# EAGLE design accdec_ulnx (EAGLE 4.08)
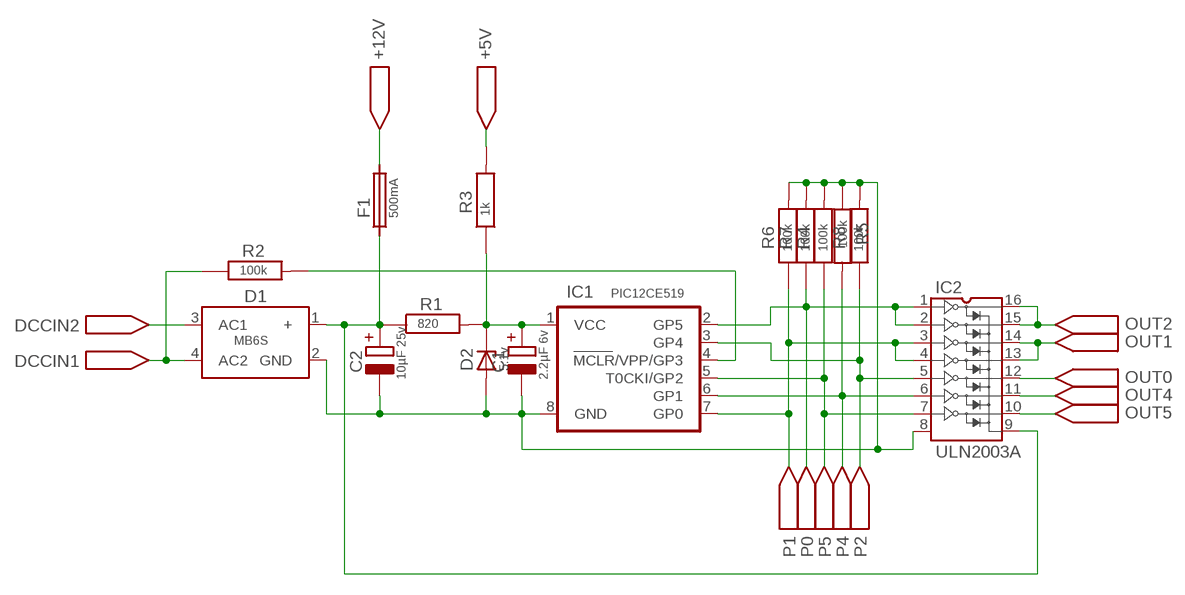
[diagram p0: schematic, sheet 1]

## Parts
+5V  PORT1*0.6  [CON_1*0.6]
+12V  PORT1.2*0.8  [CON_1.2*0.8]
C1  2.2µF 6v  ELKO_A  [CA]
C2  10µF 25v  ELKO_C  [CC]
D1  MB6S  [G1]
D2  5.1v  ZMM  [ZMM]
DCCIN1  PORT1*0.6  [CON_1*0.6]
DCCIN2  PORT1*0.6  [CON_1*0.6]
F1  500mA  FUSE  [1210]
IC1  PIC12CE519  PIC12CE519/SN  [SO8/SN]
IC2  ULN2003A  ULN2001A  [SO16]
OUT0  PORT1*0.6  [CON_1*0.6]
OUT1  PORT1*0.6  [CON_1*0.6]
OUT2  PORT1*0.6  [CON_1*0.6]
OUT4  PORT1*0.6  [CON_1*0.6]
OUT5  PORT1*0.6  [CON_1*0.6]
P0  PORT1*0.6  [CON_1*0.6]
P1  PORT1*0.6  [CON_1*0.6]
P2  PORT1*0.6  [CON_1*0.6]
P4  PORT1*0.6  [CON_1*0.6]
P5  PORT1*0.6  [CON_1*0.6]
R1  820  R-M1  [MICRO_MELF]
R2  100k  R-M1  [MICRO_MELF]
R3  1k  R-M1  [MICRO_MELF]
R4  100k  R-M1  [MICRO_MELF]
R5  100k  R-M1  [MICRO_MELF]
R6  100k  R-M1  [MICRO_MELF]
R7  100k  R-M1  [MICRO_MELF]
R8  100k  R-M1  [MICRO_MELF]

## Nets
+: C2.P$2(+) D1.1(+) F1.1 IC2.9(COM) R1.P$1
DCCIN: IC1.4(MCLR/VPP/GP3) R2.P$2
GND: C1.P$1(-) C2.P$1(-) D1.2(GND) D2.P$1(A) IC1.8(GND) IC2.8(GND) R4.P$2 R5.P$1 R6.P$2 R7.P$2 R8.P$2
GP0: IC1.7(GP0) IC2.3(IN3) IC2.4(IN4) P1.P$1 R6.P$1
GP1: IC1.6(GP1) IC2.6(IN6) P4.P$1 R5.P$2
GP2: IC1.5(T0CKI/GP2) IC2.7(IN7) P5.P$1 R4.P$1
GP4: IC1.3(GP4) IC2.5(IN5) P2.P$1 R8.P$1
GP5: IC1.2(GP5) IC2.1(IN1) IC2.2(IN2) P0.P$1 R7.P$1
N$1: D1.4(AC2) DCCIN1.P$1 R2.P$1
N$2: D1.3(AC1) DCCIN2.P$1
N$3: +5V.P$1 R3.P$2
N$4: +12V.P$1 F1.2
N$10: IC2.12(OUT5) OUT0.P$1
N$11: IC2.11(OUT6) OUT4.P$1
N$12: IC2.10(OUT7) OUT5.P$1
N$13: IC2.15(OUT2) IC2.16(OUT1) OUT2.P$1
N$14: IC2.13(OUT4) IC2.14(OUT3) OUT1.P$1
VCC: C1.P$2(+) D2.P$2(K) IC1.1(VCC) R1.P$2 R3.P$1

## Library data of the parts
+5V +12V DCCIN1 DCCIN2 OUT0 OUT1 OUT2 OUT4 OUT5 P0 P1 P2 P4 P5 = NMRA-DCC_Decoder_Parts:PORT
C1 C2 = NMRA-DCC_Decoder_Parts:ELKO
D1 = NMRA-DCC_Decoder_Parts:MB6S: Rectifier s380 & mb6s
D2 = NMRA-DCC_Decoder_Parts:ZMM: DIODE
F1 = NMRA-DCC_Decoder_Parts:FUSE
IC1 = NMRA-DCC_Decoder_Parts:PIC12C*?: PIC12Cx5xx 8 bit Microchip Microcontroller with 2k byte PROM and 16 byte EEPROM
IC2 = NMRA-DCC_Decoder_Parts:UL
R1-R8 = NMRA-DCC_Decoder_Parts:R-: Resistor

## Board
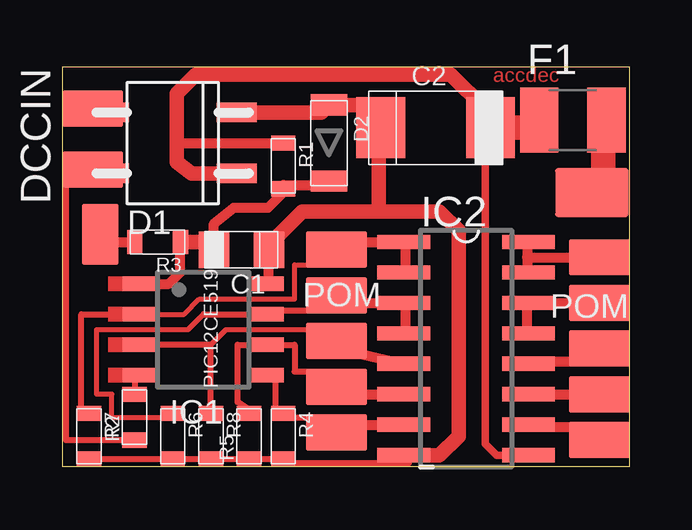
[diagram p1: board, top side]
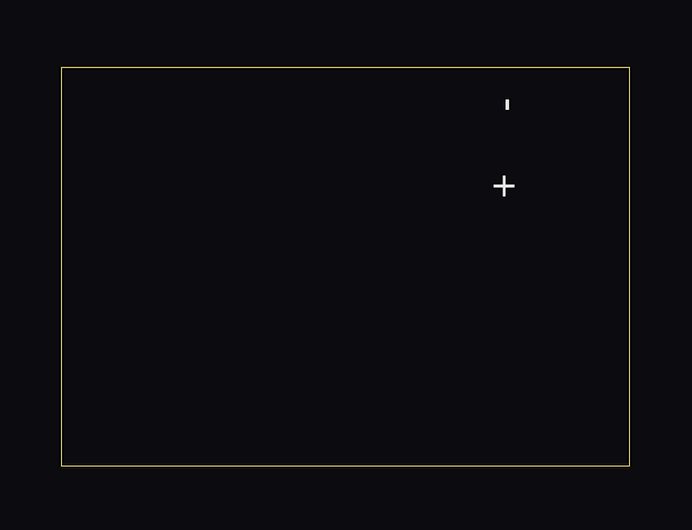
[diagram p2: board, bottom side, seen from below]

Size 23.64 x 16.66 mm. Coordinates in mm from the lower left corner, seen from the top.
Outline: 0,0 23.64,0 23.64,16.66 0,16.66 0,0
Copper layers used: Top

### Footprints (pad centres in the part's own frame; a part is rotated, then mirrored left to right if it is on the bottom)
CON_1*0.6 = smd 2.54 x 1.524: P$1 0,0
CON_1.2*0.8 = smd 3.048 x 2.032: P$1 0,0
CA = smd 1.27 x 1.524: P$1 -1.143,0; P$2 1.143,0
CC = smd 2.032 x 2.54: P$1 -2.286,0; P$2 2.286,0
G1 = smd 1.676 x 0.813: 1 3.302,-1.27; 2 3.302,1.27; 3 -2.032,1.27; 4 -2.032,-1.27
ZMM = smd 0.889 x 1.524: P$1 -1.587,0; P$2 1.587,0
1210 = smd 1.6 x 2.7: 1 -1.4,0; 2 1.4,0
SO8/SN = smd 0.61 x 1.524: 1 -1.905,-2.6; 2 -0.635,-2.6; 3 0.635,-2.6; 4 1.905,-2.6; 5 1.905,2.6; 6 0.635,2.6; 7 -0.635,2.6; 8 -1.905,2.6
SO16 = smd 0.6 x 2.2: 1 -4.445,-2.6; 2 -3.175,-2.6; 3 -1.905,-2.6; 4 -0.635,-2.6; 5 0.635,-2.6; 6 1.905,-2.6; 7 3.175,-2.6; 8 4.445,-2.6; 9 4.445,2.6; 10 3.175,2.6; 11 1.905,2.6; 12 0.635,2.6; 13 -0.635,2.6; 14 -1.905,2.6; 15 -3.175,2.6; 16 -4.445,2.6
MICRO_MELF = smd 0.635 x 1.016: P$1 -0.953,0; P$2 0.953,0

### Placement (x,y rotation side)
+5V  1.58,9.68 270 top
+12V  22.06,11.43 0 top
C1  7.46,9.04 180 top
C2  15.55,14.12 0 top
D1  3.96,13.49 0 top
D2  11.11,13.49 270 top
DCCIN1  1.26,12.38 180 top
DCCIN2  1.26,14.92 180 top
F1  21.27,14.44 0 top
IC1  5.87,5.71 270 top
IC2  16.82,4.92 270 top
OUT0  22.38,4.92 0 top
OUT1  22.38,6.82 0 top
OUT2  22.38,8.73 0 top
OUT4  22.38,3.01 0 top
OUT5  22.38,1.11 0 top
P0  11.42,9.04 0 top
P1  11.42,7.14 180 top
P2  11.42,5.23 0 top
P4  11.42,3.33 0 top
P5  11.42,1.42 0 top
R1  9.2,12.54 270 top
R2  3.01,2.06 90 top
R3  3.96,9.36 180 top
R4  9.2,1.27 270 top
R5  7.77,1.26 90 top
R6  4.6,1.27 270 top
R7  1.11,1.27 270 top
R8  6.18,1.27 270 top

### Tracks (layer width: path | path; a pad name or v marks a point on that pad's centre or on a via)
+
  Top 0.305: IC2.9 18.09,0.47 17.62,0.95 17.62,14.12
  Top 0.406: 4.76,13.49 R1.P$1 | 17.77,13.49 17.77,13.33 17.68,14.19 C2.P$2 17.77,14.28 17.77,13.49 | 17.62,14.92 17.77,13.49 | F1.1 19.84,14.12 20,13.97 19.68,14.12 | 19.68,14.12 | 19.68,14.12 | 17.62,14.12 19.68,14.12
  Top 0.61: D1.1 5.39,12.22 4.76,12.7 4.76,13.49 4.76,15.55 5.55,16.35 16.19,16.35 17.62,14.92
  Top 1.016: C2.P$2 19.68,14.12
DCCIN
  Top 0.254: IC1.4 | IC1.4 3.01,3.81 R2.P$2 | IC1.4
GND
  Top 0.254: R7.P$2 4.44,0.31 | 4.44,0.31 R6.P$2 4.44,0.31 | 4.44,0.31 R8.P$2 | R4.P$2 9.2,0.15 14.44,0.15 14.44,0.47 14.28,0.41 IC2.8 | R5.P$1 | R8.P$2 | R8.P$2 R5.P$1 | R4.P$2 R5.P$1 | R4.P$2 | R5.P$1
  Top 0.406: 8.41,9.52 C1.P$1 | 8.41,9.52 | 13.17,10.63 13.17,14.6 13.17,15.08 D2.P$1 | 8.88,9.52 8.41,9.52 | 8.41,9.52 8.57,9.2 8.57,7.62 IC1.8
  Top 0.61: 14.44,0.47 15.71,0.47 16.5,1.27 16.5,9.84 15.71,10.63 13.17,10.63 | 13.17,10.63 10,10.63 | 13.17,10.63 | 10,10.63 8.88,9.52 | 14.44,0.47 14.28,0.47 | 14.44,0.47 IC2.8 | C2.P$1 13.11,14.54 13.17,14.6 13.17,10.63 | D1.2 10.79,14.76 D2.P$1 13.17,15.08 13.17,10.63 | 13.17,10.63 | 10,10.63 13.17,10.63 | 8.41,9.52 8.57,9.52 8.73,9.36 10,10.63
GP0
  Top 0.203: 1.42,5.71 5.23,5.71 | 1.42,3.01 1.42,5.71 | 2.06,3.01 1.42,3.01 | 4.44,2.06 2.06,2.06 2.06,3.01 | 2.06,3.01 1.42,3.01 | 1.42,3.01 1.42,5.71 | 1.42,5.71 5.23,5.71 | 5.23,5.71 5.87,6.35 8.73,6.35 8.88,6.5 11.58,6.5 11.9,6.82 14.28,6.82
  Top 0.254: 11.42,6.82 P1.P$1 10.31,6.5 9.04,6.5 IC1.7 5.87,6.35 | 4.44,2.06 R6.P$1
  Top 0.406: 11.42,6.82 11.9,6.82 IC2.3 14.28,6.82 14.28,5.55 IC2.4
GP1
  Top 0.254: P4.P$1 10.79,3.96 9.68,3.96 9.68,5.08 IC1.6 7.3,5.08 7.3,2.69 7.77,2.38 R5.P$2
  Top 0.406: P4.P$1 11.42,3.01 IC2.6
GP2
  Top 0.203: IC2.7 14.28,1.74 14.22,1.8
  Top 0.254: P5.P$1 10.31,2.06 9.52,2.06 | 10.63,1.74 10.31,2.06 9.52,2.06 | 9.52,2.06 9.2,2.38 R4.P$1 8.88,2.22 8.88,3.81 IC1.5 8.41,3.81
  Top 0.406: 10.63,1.74 IC2.7
GP4
  Top 0.203: 6.18,5.08 6.82,5.71 10.95,5.71
  Top 0.254: 11.42,5.55 P2.P$1 10.95,5.71 | IC1.3 3.49,5.08 4.6,5.08 | 4.6,5.08 6.18,5.08 R8.P$1 | IC1.3 | 4.6,5.08 IC1.3
  Top 0.406: IC2.5 11.42,4.92 11.42,5.55
GP5
  Top 0.203: 10.31,8.41 9.68,8.41 9.68,6.98 5.71,6.98 5.07,6.35 3.49,6.35
  Top 0.254: 11.42,9.36 P0.P$1 10.31,8.41 | IC1.2 3.49,6.35 | IC1.2 | IC1.2 0.79,6.35 0.79,2.38 1.11,2.38 R7.P$1
  Top 0.406: 11.42,9.36 IC2.1 14.28,9.36 14.28,8.09 IC2.2
N$1
  Top 0.254: R2.P$1 0.15,1.11 0.15,12.54 DCCIN1.P$1
  Top 0.406: D1.4 1.9,12.22 1.74,12.38 DCCIN1.P$1
  Top 0.61: DCCIN1.P$1 | DCCIN1.P$1
N$2
  Top 0.406: D1.3 1.74,14.76 1.58,14.92 DCCIN2.P$1
N$3
  Top 0.406: R3.P$2 | +5V.P$1 1.58,9.36 R3.P$2
N$4
  Top 0.406: +12V.P$1 22.54,11.74
  Top 1.016: 22.54,11.74 22.54,14.44 22.54,14.76 F1.2
N$10
  Top 0.406: OUT0.P$1 21.38,4.38 20.11,4.38 IC2.12 19.36,4.28
N$11
  Top 0.406: IC2.11 OUT4.P$1
N$12
  Top 0.203: OUT5.P$1 22.22,1.11 21.58,1.66
  Top 0.406: IC2.10 20.25,1.66 21.36,1.66 OUT5.P$1 21.58,1.58 21.58,1.66
N$13
  Top 0.406: IC2.16 19.36,9.36 19.36,8.73 | 19.36,8.25 19.36,8.09 IC2.15 19.36,8.25 | 19.36,8.73 OUT2.P$1 | 19.36,8.73 19.36,8.25
N$14
  Top 0.406: OUT1.P$1 IC2.14 19.36,6.82 19.36,5.55 IC2.13
VCC
  Top 0.406: IC1.1 4.44,7.62 4.91,8.09 R3.P$1 | C1.P$2 6.31,10.12 7.14,10.79 8.57,10.79 9.36,11.58 R1.P$2 9.04,11.58 9.2,11.74 10.95,11.74 10.95,11.9
  Top 0.61: C1.P$2 6.34,9.04 6.5,9.36 R3.P$1 | 10.95,11.9 | 10.95,11.9 D2.P$2
(copper drawn outside any net)
  shapes: Top area x4

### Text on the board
Top: accdec
tPlace: DCCIN | POM | POM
